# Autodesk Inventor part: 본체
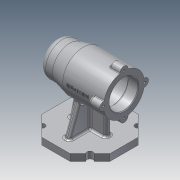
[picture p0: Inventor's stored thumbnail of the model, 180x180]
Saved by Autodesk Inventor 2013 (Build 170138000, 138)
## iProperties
Created: 2021-01
Part Number: 본체
Material: 알루미늄 6061
Document SubType Name: Modeling
Designer: user
Density: 2.71 g/cm^3
Mass: 632.298 g
Surface Area: 613.789 cm^2
Volume: 233.32 cm^3
Author: user
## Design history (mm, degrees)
sketch "스케치1"
  geometry: L1 (0, 0)-(100, 0); L2 (100, 0)-(100, 30); L3 (100, 30)-(40, 30); L4 (40, 30)-(20, 25); L5 (20, 25)-(0, 25); L6 (0, 25)-(0, 0)
  constraints: 12 end point, 2 parallel, 2 perpendicular, 1 horizontal
  dimensions: "d0" = 100 distance of L1.start L1.end; "d1" = 60 diameter of L3 L1; "d2" = 50 diameter of L5 L1; "d3" = 20 distance of L5.end L4.end; "d4" = 40 horizontal distance of L5.end L3.end
revolve "회전1" sketch "스케치1" stored, may be unused: angle "d5" = 90 deg
sketch "스케치2"
  geometry: L1 (0, -25)-(0, 25) reference; L2 (0, 25)-(20, 25) reference; L3 (20, 25)-(40, 30) reference; L4 (40, 30)-(100, 30) reference; L5 (100, 30)-(100, -30) reference; L6 (100, -30)-(40, -30) reference; L7 (40, -30)-(20, -25) reference; L8 (20, -25)-(0, -25) reference; L9 (100, 0)-(6, 0); L10 (100, 0)-(100, 21); L11 (100, 21)-(85, 21); L12 (85, 21)-(85, 24); L13 (85, 24)-(43, 24); L14 (43, 24)-(43, 21); L15 (43, 21)-(31, 21); L16 (31, 21)-(31, 17.5); L17 (31, 17.5)-(13, 17.5); L18 (13, 17.5)-(13, 16); L19 (13, 16)-(9, 16); L20 (9, 16)-(9, 10.5); L21 (9, 10.5)-(6, 10.5); L22 (6, 10.5)-(6, 0); 1 further point
  constraints: 28 end point, 9 parallel, 4 perpendicular, 1 collinear, 1 midpoint, 1 point on line
  dimensions: "d6" = 42 diameter of L11 L9; "d8" = 48 diameter of L13 L9; "d9" = 21 diameter of L21 L9; "d10" = 32 diameter of L19 L9; "d11" = 35 diameter of L17 L9; "d12" = 42 diameter of L15 L9; "d13" = 15 distance of L10.end L11.end; "d14" = 42 distance of L12.end L13.end; "d15" = 12 distance of L14.end L15.end; "d16" = 18 distance of L16.end L17.end; "d17" = 4 distance of L18.end L19.end; "d18" = 3 distance of L20.end L21.end
revolve "회전2" sketch "스케치2" stored, may be unused: angle "d19" = 90 deg
fillet "모깎기1" dims "d20" = 0.3
fillet "모깎기2" dims "d21" = 10
sketch "스케치3"
  geometry: C1 r 6 at (0, 30); 1 further point
  constraints: 1 centre point, 1 vertical alignment, 1 other
  dimensions: "d22" = 6 radius of C1
extrude "돌출1" join sketch "스케치3" distance "d23" = 16; taper "d24" = 0 deg
sketch "스케치4"
  geometry: A1 r 6 centre (0, 0) between (5.97, -0.6) and (-5.97, -0.6) reference; 1 further point
  constraints: 1 coincident
hole "구멍1" sketch "스케치4" at (0, 0) diameter "d25" = 3.242; stored, may be unused: countersink angle "d29" = 90 deg, drill point angle "d31" = 118 deg; dims "d26" = 8, "d27" = 4, "d28" = 2, "d30" = 10
node "작업 평면1"
sketch "스케치5" dims "d36" = 50
  geometry: L1 (-100, -6)-(-100, 6) reference; L2 (-70.711, -50)-(-100, -20.711); L3 (-100, -20.711)-(-100, 20.711); L4 (-100, 20.711)-(-70.711, 50); L5 (-70.711, 50)-(-29.289, 50); L6 (-29.289, 50)-(0, 20.711); L7 (0, 20.711)-(0, -20.711); L8 (0, -20.711)-(-29.289, -50); L9 (-29.289, -50)-(-70.711, -50); 6 further points
  constraints: 16 end point, 2 vertical alignment, 1 coincident, 1 horizontal alignment, 1 midpoint, 1 vertical, 19 other
extrude "돌출2" join sketch "스케치5" distance "d37" = 10; taper "d38" = 0 deg
sketch "스케치7"
  geometry: L1 (100, 20.711)-(70.711, 50) reference; L2 (29.289, 50)-(0, 20.711) reference; L3 (0, -20.711)-(29.289, -50) reference; L4 (70.711, -50)-(100, -20.711) reference; 5 further points
  constraints: 4 midpoint
hole "구멍2" sketch "스케치7" at (14.645, 35.355), (14.645, -35.355), (85.355, -35.355), (85.355, 35.355) diameter "d42" = 9; stored, may be unused: countersink angle "d46" = 90 deg, drill point angle "d48" = 118 deg; dims "d43" = 8, "d44" = 4, "d45" = 2, "d47" = 10
sketch "스케치8"
  geometry: L1 (100, -20.711)-(100, 20.711) reference; L2 (0, 20.711)-(0, -20.711) reference; L3 (23, 4)-(77, 4); L4 (77, 4)-(77, -4); L5 (77, -4)-(23, -4); L6 (23, -4)-(23, 4); 3 further points
  constraints: 8 end point, 2 midpoint, 2 parallel, 1 horizontal, 1 horizontal alignment, 1 perpendicular
  dimensions: "d49" = 8 distance between parallel lines of L3 L5; "d51" = 23 distance between parallel lines of L1 L4; "d52" = 23 distance between parallel lines of L2 L6
extrude "돌출4" join sketch "스케치8" stored distance "d53" = 10; taper "d54" = 0 deg
feature "면 기울기1" dims angle "d55" = 11 deg
node "작업 평면2"
sketch "스케치9"
  geometry: L1 (-75, -50)-(-75, 50) reference; L2 (-75, 50)-(-65, 50) reference; L3 (-65, 50)-(-65, 4) reference; L4 (-65, 4)-(-29.732, 4) reference; L5 (-29.732, -4)-(-65, -4) reference; L6 (-65, -4)-(-65, -50) reference; L7 (-65, -50)-(-75, -50) reference; L8 (-65, 35)-(-22.707, 19.606); C1 r 24 at (0, 0) reference; A1 r 30 centre (0, 0) between (-29.732, -4) and (-29.732, 4) reference; 1 further point
  constraints: 2 end point, 1 point on circle, 1 point on line
  dimensions: "d57" = 15 distance from line of L2 L8.start; "d58" = 110 deg angle of L8 L3
feature "리브1" sketch "스케치9" dims "d59" = 1, "d60" = 8, "d61" = 0, "d62" = 0, "d63" = 1, "d64" = 1
fillet "모깎기3" dims "d65" = 3
fillet "모깎기4" dims "d66" = 1
fillet "모깎기5" dims "d67" = 3
fillet "모깎기6" dims "d68" = 3
node "작업 평면3"
sketch "스케치10"
  geometry: L1 (100, 36)-(100, 30.171) reference; 2 further points
  constraints: 1 horizontal alignment, 1 other
  dimensions: "d70" = 38 distance from line of L1 point (62, 0)
feature "엠보싱1" sketch "스케치10" dims "d0" = 100, "d1" = 60, "d2" = 50, "d3" = 20, "d4" = 40, "d71" = 0.5, "d72" = 0
chamfer "모따기1" distance "d73" = 1; stored, may be unused: second distance "d74" = 2, angle "d75" = 45 deg
node "솔리드1"
pattern_circular "원형 패턴1" dims angle "d33" = 360 deg
mirror "대칭1"
node "절단 모서리 투영1"
node "절단 모서리 투영2"
other parameters: "d35" = -75
